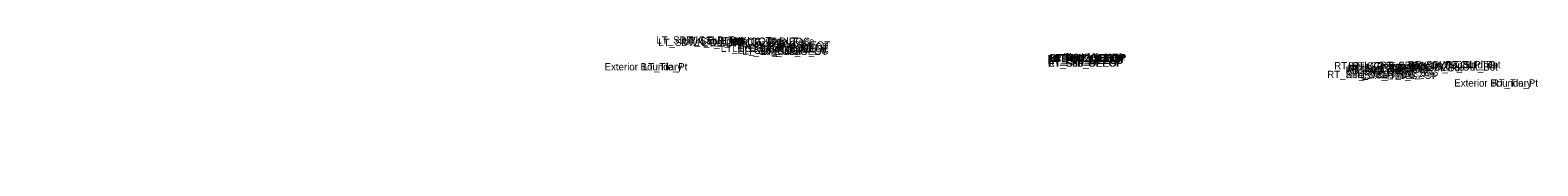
# Model space of a CAD drawing. Extents: x -26 to 6300, y -10 to 9528.
# Drawn here: x 1000 to 1208.4, y 4500 to 4517.1 of the extents above; entities that cross this region are included whole.
import ezdxf

# ---------------------------------------------------------------- set-up
doc = ezdxf.new("R2010")
doc.units = 0
doc.layers.add('Default', color=7, linetype='Continuous')

msp = doc.modelspace()

# ---------------------------------------------------------------- texts
at = {"layer": 'Default'}
for s, height, p in [('LT_SDWK_Out_Top', 1, (1086.58, 4516.05)), ('LT_CSLP_Pnt', 1, (1090.1, 4516.05)), ('LT_Sub_Trench_Out_DLT', 1, (1090.32, 4515.9)), ('LT_SDWK_In_Top', 1, (1092.74, 4515.95)), ('LT_CG_Top_BOC', 1, (1096.81, 4515.86)), ('LT_CG_Top_Face', 1, (1097.34, 4515.86)), ('LT_SDWK_Out_Bot', 1, (1086.83, 4515.72)), ('LT_SDWK_In_Bot', 1, (1092.99, 4515.62)), ('LT_CG1_Shelf_Out', 1, (1095.48, 4514.9)), ('LT_CG_Bot_BOC', 1, (1097.09, 4514.88)), ('LT_Sub_OEOP', 1, (1097.79, 4514.66)), ('LT_CG_Top_Gut', 1, (1097.87, 4515.36)), ('LT_Sub_OEOT_CG', 1, (1098.44, 4514.53)), ('LT_PV2_OEOT', 1, (1100.99, 4515.11)), ('LT_PV3_OEOT', 1, (1100.99, 4514.86)), ('LT_Sub_OEOT', 1, (1101.04, 4514.48)), ('LT_PV1_OEOT', 1, (1101.23, 4515.36)), ('LT_CG_Bot_IE', 1, (1101.34, 4514.78)), ('Exterior Boundary', 1, (1079.42, 4512.35)), ('LT_Tie_Pt', 1, (1084.7, 4512.35)), ('RT_PV2_OEEOP', 1, (1140.67, 4513.49)), ('RT_PV3_OEEOP', 1, (1140.67, 4513.24)), ('RT_Sub_OEEOP', 1, (1140.71, 4512.86)), ('LT_PV2_OEEOP', 1, (1140.79, 4513.49)), ('LT_PV3_OEEOP', 1, (1140.79, 4513.24)), ('LT_Sub_OEEOP', 1, (1140.83, 4512.86)), ('RT_PV1_OEEOP', 1, (1140.91, 4513.61)), ('LT_PV1_OEEOP', 1, (1141.02, 4513.61)), ('RT_PV2_IEEOP', 1, (1141.43, 4513.49)), ('LT_PV2_IEEOP', 1, (1141.55, 4513.49)), ('RT_PV1_IEEOP', 1, (1141.67, 4513.61)), ('LT_PV1_IEEOP', 1, (1141.79, 4513.61)), ('RT_PV2_PGL', 1, (1142.65, 4513.49)), ('LT_PV2_PGL', 1, (1142.76, 4513.49)), ('RT_PV1_PGL', 1, (1142.88, 4513.74)), ('LT_PV1_PGL', 1, (1143, 4513.74)), ('RT_Sub_Trench_Out_DLT', 1, (1180.29, 4512.5)), ('RT_PV2_OEOT', 1, (1181.87, 4511.87)), ('RT_PV1_OEOT', 1, (1182.11, 4512.12)), ('RT_CG_Top_Face', 1, (1182.22, 4512.46)), ('RT_CG_Top_BOC', 1, (1182.69, 4512.46)), ('RT_CG_Top_Gut', 1, (1182.75, 4511.96)), ('RT_SDWK_In_Top', 1, (1186.62, 4512.55)), ('RT_SDWK_In_Bot', 1, (1186.87, 4512.22)), ('RT_SDWK_Out_Top', 1, (1190.46, 4512.65)), ('RT_SDWK_Out_Bot', 1, (1190.71, 4512.32)), ('RT_Shld_O', 1, (1195.63, 4512.64)), ('CSLP_Pnt', 1, (1197.04, 4512.65)), ('RT_Sub_OEOT_CG', 1, (1179.32, 4511.29)), ('RT_PV3_OEOT', 1, (1181.87, 4511.62)), ('RT_Sub_OEOT', 1, (1181.92, 4511.24)), ('RT_CG_Bot_IE', 1, (1182.22, 4511.54)), ('RT_CG1_Shelf_Out', 1, (1182.36, 4511.42)), ('RT_CG_Bot_BOC', 1, (1182.97, 4511.44)), ('RT_Sub_OEOP', 1, (1185.17, 4511.16)), ('Exterior Boundary', 1, (1196.89, 4510.11)), ('RT_Tie_Pt', 1, (1202.06, 4510.11)), ('-', 0.0001, (1000, 4500))]:
    msp.add_text(s, height=height, dxfattribs=at).set_placement(p)

doc.saveas('drawing.dxf')
